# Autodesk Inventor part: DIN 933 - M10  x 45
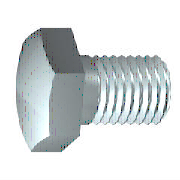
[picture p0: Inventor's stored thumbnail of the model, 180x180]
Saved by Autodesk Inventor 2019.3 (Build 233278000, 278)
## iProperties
Created: 2018-01
Part Number: DIN 933 - M10  x 45
Material: Ocel, měkká
Description: Šestihranný šroub
Document SubType Name: Modeling
Standard: DIN 933
Designer: B-hon
Standards Organization: DIN
Language: cs-CZ
Size Designation: M10  x 45
Categories: <MemberInstance><Categories><Category DisplayName="Spojovací materiál" InternalName="e4da775c-781d-43d5-af7c-5136215cf5a6" Mnemonic="FSTN"><Category DisplayName
Density: 7.85 g/cm^3
Appearance: Pololeštěná
IsCustomPart: 0
Author: B-hon
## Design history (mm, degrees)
sketch "Náčrt1"
  geometry: L1 (0, 7.7)-(0, 4.594); L2 (4.5, 5)-(45, 5); L3 (45, 5)-(45, 0); L4 (45, 0)-(-0.6, 0); L5 (-9.72, 0)-(54.12, 0) reference; L6 (-0.6, 0)-(-0.6, 7.7); L7 (-0.6, 7.7)-(0, 7.7); L8 (4.5, 5)-(3.58, 4.594); L9 (3.58, 4.594)-(0, 4.594); L10 (0, -1.54)-(0, 9.24) reference
  constraints: 16 end point, 2 collinear, 2 perpendicular, 1 parallel
  dimensions: "d0" = 45 distance between parallel lines of L3 L1 (= NLG); "d1" = 40.5 distance from line of L2.start L3 (= GEL); "d2" = 10 diameter of L2 L4 (= GD); "d9" = 0.6001 distance between parallel lines of L6 L1 (computed from SD); "d10" = 15.4 diameter of L7 L4 (= SD2); "d13" = 0.92028 horizontal distance of L2.start L8.end (computed from GAL); "d14" = 9.1881 diameter of L9 L4 (= BDM)
revolve "Těleso" sketch "Náčrt1" stored, may be unused: angle "d12" = 90 deg
sketch "Náčrt2"
  geometry: L1 (0, 9.815)-(8.5, 4.907); L2 (8.5, 4.907)-(8.5, -4.907); L3 (8.5, -4.907)-(0, -9.815); L4 (0, -9.815)-(-8.5, -4.907); L5 (-8.5, -4.907)-(-8.5, 4.907); L6 (-8.5, 4.907)-(0, 9.815); 2 further points
  constraints: 12 end point, 1 coincident, 1 vertical, 11 other
  dimensions: "d11" = 17 distance between parallel lines of L5 L2 (= SW)
extrude "Hlava" join sketch "Náčrt2" distance "d3" = 5.8 (= KOH - SD); taper "d4" = 0 deg
sketch "Náčrt4"
  geometry: L1 (-6.4, 8.5)-(-6.4, 9.815); L2 (-6.4, 9.815)-(-5.641, 9.815); L3 (-5.641, 9.815)-(-6.4, 8.5); L4 (-7.56, 0)-(0.56, 0) reference; L5 (-0.6, 9.815)-(-6.4, 9.815) reference; L6 (-6.4, 4.907)-(-6.4, 9.815) reference
  constraints: 6 end point, 2 collinear, 1 perpendicular, 1 vertical
  dimensions: "d5" = 30 deg angle of L3 L1 (= ANG1); "d19" = 17 diameter of L1.start L4 (= SW0)
revolve "Zkosení1" sketch "Náčrt4" stored, may be unused: angle "d21" = 90 deg
workplane "Work Plane1"
body "Solid1"
feature "Závit" dims "d15" = 40.5 (= GEL), "d16" = 0
chamfer "Zkosení2" distance "d6" = 0.92018 (= -0.5 x SPD + 0.5 x GD); stored, may be unused: second distance "d7" = 0.92028 (computed from GUL), angle "d55" = 45 deg
other parameters: "NLG" = 45 [user parameter; used in 1 equation term], "GD" = 10 (= NND) [user parameter; used in 2 equation terms], "BDM" = 9.1881 [user parameter; used in 1 equation term], "KOH" = 6.4 [user parameter; used in 1 equation term], "GEL" = 40.5 [user parameter; used in 2 equation terms], "SW" = 17 [user parameter; used in 2 equation terms], "SW0" = 17 [user parameter; used in 1 equation term], "SPD" = 8.15965 (= NND - 1.2269 x PTC) [user parameter; used in 1 equation term], "SD2" = 15.4 [user parameter; used in 1 equation term], "SD" = 0.6 [user parameter; used in 2 equation terms], "ANG1" = 30 deg [user parameter; used in 1 equation term], "GAL" = 0.92018 (= 0.61345 x PTC) [user parameter; used in 1 equation term], "GUL" = 0.92018 (= 0.61345 x PTC) [user parameter; used in 1 equation term], "d8" = 0, "RR" = 0.4 [user parameter], "d57" = 0, "d58" = 0, "TPU" = 6.66667 (computed from PTC) [user parameter], "GD1" = 8.15965 (= THREADDIA - 1.2269 x PTC) [user parameter], "TOA" = 30 deg [user parameter], "PTC" = 1.5 [user parameter; used in 5 equation terms], "E0" = 19.635 (= 1.155 x SW) [user parameter]
